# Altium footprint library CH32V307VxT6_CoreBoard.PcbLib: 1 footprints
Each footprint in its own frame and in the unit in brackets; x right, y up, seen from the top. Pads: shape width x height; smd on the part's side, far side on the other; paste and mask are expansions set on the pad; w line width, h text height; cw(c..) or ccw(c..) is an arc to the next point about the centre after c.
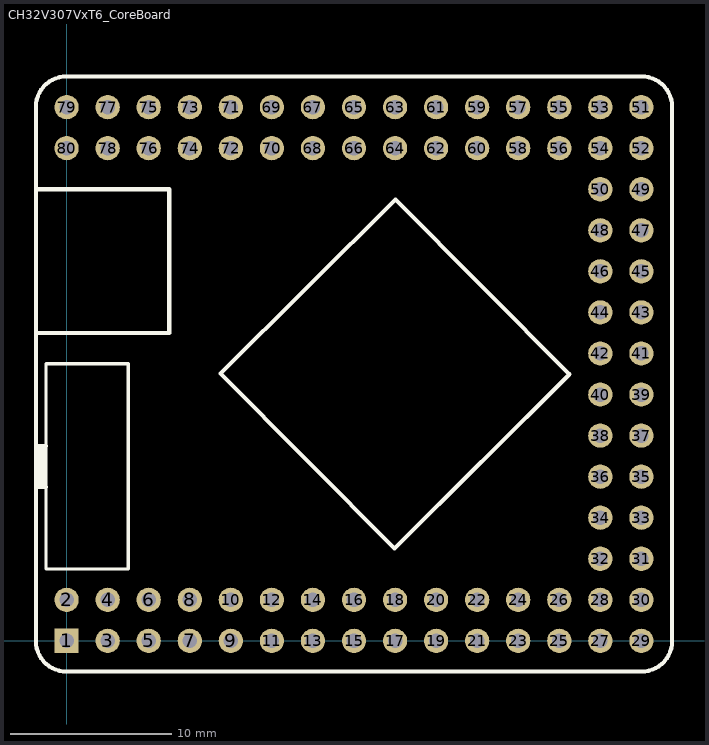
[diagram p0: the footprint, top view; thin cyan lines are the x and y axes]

## CH32V307VxT6_CoreBoard [mm] "逐飞科技CH32V307VxT6核心板"
pads (80):
  rect 1.5x1.5 hole 0.9: 1(0,0)
  round 1.5 hole 0.9: 2(0,2.54) 3(2.54,0) 4(2.54,2.54) 5(5.08,0) 6(5.08,2.54) 7(7.62,0) 8(7.62,2.54) 9(10.16,0) 10(10.16,2.54) 11(12.7,0) 12(12.7,2.54) 13(15.24,0) 14(15.24,2.54) 15(17.78,0) 16(17.78,2.54) 17(20.32,0) 18(20.32,2.54) 19(22.86,0) 20(22.86,2.54) 21(25.4,0) 22(25.4,2.54) 23(27.94,0) 24(27.94,2.54) 25(30.48,0) 26(30.48,2.54) 27(33.02,0) 28(33.02,2.54) 29(35.56,0) 30(35.56,2.54) 31(35.56,5.08) 32(33.02,5.08) 33(35.56,7.62) 34(33.02,7.62) 35(35.56,10.16) 36(33.02,10.16) 37(35.56,12.7) 38(33.02,12.7) 39(35.56,15.24) 40(33.02,15.24) 41(35.56,17.78) 42(33.02,17.78) 43(35.56,20.32) 44(33.02,20.32) 45(35.56,22.86) 46(33.02,22.86) 47(35.56,25.4) 48(33.02,25.4) 49(35.56,27.94) 50(33.02,27.94) 51(35.56,33.02) 52(35.56,30.48) 53(33.02,33.02) 54(33.02,30.48) 55(30.48,33.02) 56(30.48,30.48) 57(27.94,33.02) 58(27.94,30.48) 59(25.4,33.02) 60(25.4,30.48) 61(22.86,33.02) 62(22.86,30.48) 63(20.32,33.02) 64(20.32,30.48) 65(17.78,33.02) 66(17.78,30.48) 67(15.24,33.02) 68(15.24,30.48) 69(12.7,33.02) 70(12.7,30.48) 71(10.16,33.02) 72(10.16,30.48) 73(7.62,33.02) 74(7.62,30.48) 75(5.08,33.02) 76(5.08,30.48) 77(2.54,33.02) 78(2.54,30.48) 79(0,33.02) 80(0,30.48)
Top Overlay:
  lines w0.2: -1.27,4.445 3.81,4.445 3.81,17.145 -1.27,17.145 -1.27,4.445
  lines w0.254: -1.905,19.05 6.35,19.05 6.35,27.94 -1.905,27.94 ; -1.651,9.525 -1.651,12.065 ; -1.397,9.525 -1.397,12.065 ; -1.27,9.525 -1.905,9.525 -1.905,12.065 -1.27,12.065 ; -1.905,0 ccw(c0,0) 0,-1.905 35.56,-1.905 ccw(c35.56,0) 37.465,0 37.465,33.02 ccw(c35.56,33.02) 35.56,34.925 0,34.925 ccw(c0,33.02) -1.905,33.02 -1.905,0 ; 9.529,16.534 20.292,5.724 31.109,16.493 20.347,27.304 9.529,16.534
3D body "CH32V307VxT6_CoreBoard.step": height 13.54, standoff -3.95, extent -1.925,-1.905 37.465,34.925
